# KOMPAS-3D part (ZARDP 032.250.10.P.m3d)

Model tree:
1. Булева операция:1
2. Булева операция:2
3. Булева операция:3
4. Булева операция:4
5. Булева операция:5
6. Булева операция:6
7. Булева операция:7
8. Булева операция:8
9. Булева операция:9
10. Булева операция:10
11. Булева операция:11
12. Булева операция:12
13. Булева операция:13
14. Булева операция:14
15. Булева операция:15
16. Булева операция:16
17. Булева операция:17
18. Булева операция:18
19. Булева операция:19
20. Булева операция:20
21. Булева операция:21
22. Булева операция:22

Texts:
  ООО ИК Энерпред-Ярдос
